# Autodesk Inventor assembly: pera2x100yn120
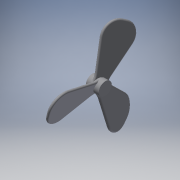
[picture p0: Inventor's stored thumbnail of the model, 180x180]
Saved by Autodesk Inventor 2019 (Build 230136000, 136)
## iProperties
Created: 2020-08
Part Number: pera2x100yn120
Material: 一般
Document SubType Name: Assembly
Designer: kikut
Author: kikut
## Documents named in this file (2)
- F:\openFOAM\bathrobo\bathrobo03.2\laminar\oversetmeshpera2\CAD\pera2x100yn120.iam
- F:\openFOAM\bathrobo\bathrobo03.2\laminar\oversetmeshpera2\CAD\pera02.ipt
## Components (1 placed, 1 different names)
1. pera02:1 — メイト:1, メイト:2
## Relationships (2: Mate 2)
- メイト:1 [Mate]: pera02:1
- メイト:2 [Mate]: pera02:1
